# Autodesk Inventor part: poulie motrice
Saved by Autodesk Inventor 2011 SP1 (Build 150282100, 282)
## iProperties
Created: 2010-12
Part Number: poulie motrice
Document SubType Name: Modeling
Designer: eric
Density: 1 g/cm^3
Author: eric
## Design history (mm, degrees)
feature "Base1"
node "Solide1"
node "Corps solides"
node "Corps surfaciques"
